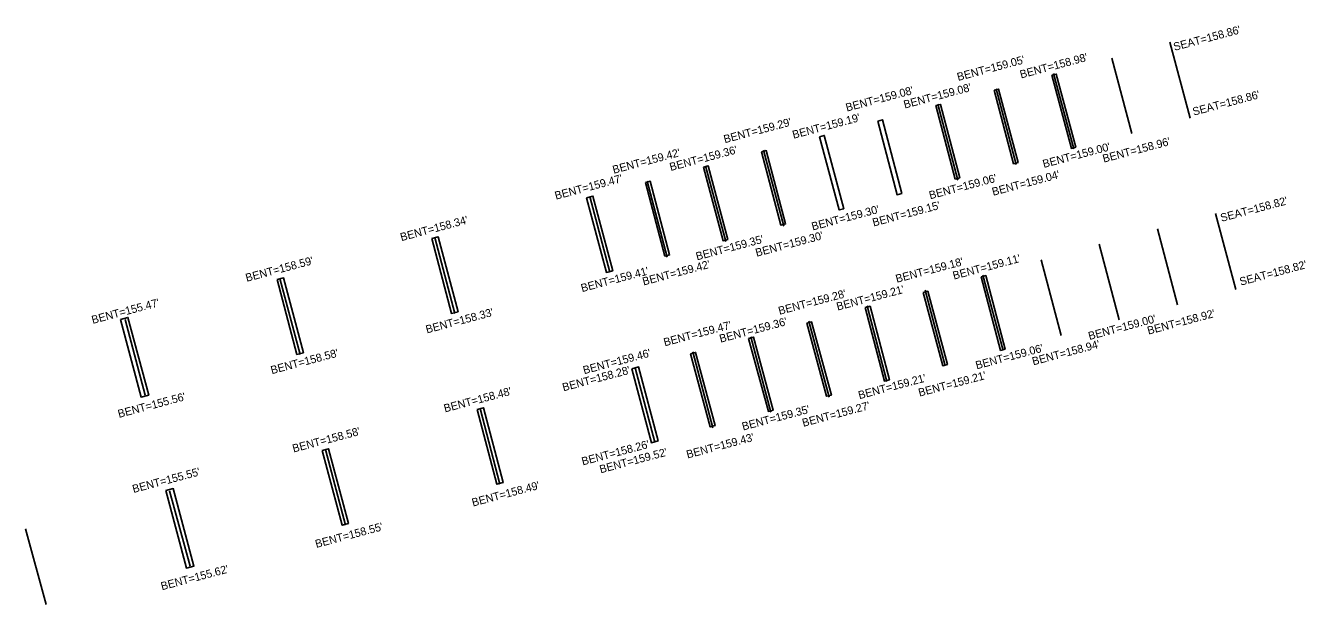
# Model space of a CAD drawing. Extents: x 2107167 to 2121551, y 865392 to 868477.
# Drawn here: x 2112084 to 2112723, y 867618 to 867908 of the extents above; entities that cross this region are included whole.
import ezdxf

# ---------------------------------------------------------------- set-up
doc = ezdxf.new("R2010")
doc.units = 0
for name, color, linetype in [('RD_EX_Bridge', 7, 'Continuous'), ('RD_EX_Bridge_txCode', 7, 'Continuous'), ('RD_EX_Conc', 7, 'Continuous')]:
    doc.layers.add(name, color=color, linetype=linetype)

msp = doc.modelspace()

# ---------------------------------------------------------------- linework, layer by layer
at = {"layer": 'RD_EX_Bridge'}
for p, q in [((2112655.33, 867899.22), (2112665.36, 867861.19)), ((2112626.2, 867891.32), (2112636.31, 867853.57)), ((2112597.18, 867883.66), (2112607.33, 867845.89)), ((2112568.42, 867875.92), (2112578.45, 867838.13)), ((2112539.39, 867868.24), (2112549.25, 867830.22)), ((2112452.27, 867845.19), (2112462.32, 867807.31)), ((2112423.24, 867837.47), (2112433.33, 867799.58)), ((2112394.16, 867829.78), (2112404.13, 867791.79)), ((2112365.42, 867822.14), (2112375.46, 867784.24)), ((2112678.14, 867813.68), (2112688.2, 867775.73)), ((2112287.94, 867801.6), (2112297.96, 867763.7)), ((2112659.13, 867768.06), (2112649.04, 867805.9)), ((2112630.01, 867760.43), (2112620, 867798.22)), ((2112600.87, 867752.72), (2112590.94, 867790.46)), ((2112210.58, 867781.17), (2112220.68, 867743.21)), ((2112571.89, 867745.14), (2112561.89, 867782.8)), ((2112542.94, 867737.45), (2112532.97, 867775.26)), ((2112513.88, 867729.71), (2112503.96, 867767.52)), ((2112133.18, 867760.62), (2112143.25, 867722.9)), ((2112484.98, 867721.93), (2112474.95, 867759.78)), ((2112455.9, 867714.38), (2112445.93, 867752.04)), ((2112426.98, 867706.59), (2112416.86, 867744.51)), ((2112397.97, 867699.38), (2112388.05, 867736.49)), ((2112310.62, 867716.13), (2112320.52, 867678.33)), ((2112233.3, 867695.72), (2112243.27, 867657.92)), ((2112155.42, 867675), (2112165.7, 867637.36)), ((2112083.5, 867656.11), (2112093.72, 867618.3))]:
    msp.add_line(p, q, dxfattribs=at)
at = {"layer": 'RD_EX_Conc'}
for points in [[(2112596.27, 867882.68), (2112606.05, 867846.14), (2112608.25, 867846.73), (2112598.46, 867883.26)], [(2112596.27, 867882.68), (2112606.05, 867846.14), (2112608.25, 867846.73), (2112598.46, 867883.26)], [(2112567.44, 867875.19), (2112577.18, 867838.48), (2112579.45, 867839.08), (2112569.7, 867875.79)], [(2112567.44, 867875.19), (2112577.18, 867838.48), (2112579.45, 867839.08), (2112569.7, 867875.79)], [(2112547.95, 867830.86), (2112538.4, 867867.51), (2112540.7, 867868.11), (2112550.26, 867831.46)], [(2112547.95, 867830.86), (2112538.4, 867867.51), (2112540.7, 867868.11), (2112550.26, 867831.46)], [(2112509.37, 867859.84), (2112519, 867823.03), (2112521.26, 867823.62), (2112511.63, 867860.43)], [(2112509.37, 867859.84), (2112519, 867823.03), (2112521.26, 867823.62), (2112511.63, 867860.43)], [(2112480.25, 867851.99), (2112490.04, 867815.38), (2112492.34, 867816), (2112482.55, 867852.6)], [(2112480.25, 867851.99), (2112490.04, 867815.38), (2112492.34, 867816), (2112482.55, 867852.6)], [(2112451.23, 867844.39), (2112460.87, 867807.81), (2112463.27, 867808.44), (2112453.63, 867845.03)], [(2112451.23, 867844.39), (2112460.87, 867807.81), (2112463.27, 867808.44), (2112453.63, 867845.03)], [(2112422.27, 867836.78), (2112432.01, 867800.03), (2112434.34, 867800.65), (2112424.6, 867837.39)], [(2112422.27, 867836.78), (2112432.01, 867800.03), (2112434.34, 867800.65), (2112424.6, 867837.39)], [(2112393.25, 867829.12), (2112402.96, 867792.33), (2112405.3, 867792.95), (2112395.59, 867829.74)], [(2112393.25, 867829.12), (2112402.96, 867792.33), (2112405.3, 867792.95), (2112395.59, 867829.74)], [(2112363.82, 867821.51), (2112373.74, 867784.21), (2112376.89, 867785.05), (2112366.96, 867822.35)], [(2112363.82, 867821.51), (2112373.74, 867784.21), (2112376.89, 867785.05), (2112366.96, 867822.35)], [(2112286.42, 867801.07), (2112296.29, 867763.7), (2112299.57, 867764.56), (2112289.7, 867801.93)], [(2112286.42, 867801.07), (2112296.29, 867763.7), (2112299.57, 867764.56), (2112289.7, 867801.93)], [(2112209.17, 867780.6), (2112219.11, 867743.19), (2112222.34, 867744.04), (2112212.39, 867781.45)], [(2112209.17, 867780.6), (2112219.11, 867743.19), (2112222.34, 867744.04), (2112212.39, 867781.45)], [(2112560.95, 867782.03), (2112570.65, 867745.22), (2112572.97, 867745.83), (2112563.27, 867782.64)], [(2112560.95, 867782.03), (2112570.65, 867745.22), (2112572.97, 867745.83), (2112563.27, 867782.64)], [(2112531.97, 867774.16), (2112541.78, 867737.55), (2112544.12, 867738.18), (2112534.3, 867774.79)], [(2112531.97, 867774.16), (2112541.78, 867737.55), (2112544.12, 867738.18), (2112534.3, 867774.79)], [(2112503.04, 867766.67), (2112512.66, 867729.88), (2112515.12, 867730.52), (2112505.49, 867767.31)], [(2112503.04, 867766.67), (2112512.66, 867729.88), (2112515.12, 867730.52), (2112505.49, 867767.31)], [(2112130.86, 867760.72), (2112141.23, 867721.88), (2112145.01, 867722.89), (2112134.64, 867761.73)], [(2112130.86, 867760.72), (2112141.23, 867721.88), (2112145.01, 867722.89), (2112134.64, 867761.73)], [(2112473.83, 867758.83), (2112483.69, 867722.27), (2112486.14, 867722.93), (2112476.27, 867759.49)], [(2112473.83, 867758.83), (2112483.69, 867722.27), (2112486.14, 867722.93), (2112476.27, 867759.49)], [(2112444.79, 867751.17), (2112454.67, 867714.69), (2112457.1, 867715.35), (2112447.22, 867751.83)], [(2112444.79, 867751.17), (2112454.67, 867714.69), (2112457.1, 867715.35), (2112447.22, 867751.83)], [(2112415.77, 867743.58), (2112425.64, 867707), (2112428.1, 867707.66), (2112418.24, 867744.24)], [(2112415.77, 867743.58), (2112425.64, 867707), (2112428.1, 867707.66), (2112418.24, 867744.24)], [(2112386.44, 867736.06), (2112396.24, 867699.08), (2112399.56, 867699.96), (2112389.76, 867736.94)], [(2112386.44, 867736.06), (2112396.24, 867699.08), (2112399.56, 867699.96), (2112389.76, 867736.94)], [(2112309.07, 867715.72), (2112318.99, 867678.35), (2112322.15, 867679.19), (2112312.23, 867716.56)], [(2112309.07, 867715.72), (2112318.99, 867678.35), (2112322.15, 867679.19), (2112312.23, 867716.56)], [(2112231.76, 867695.21), (2112241.69, 867657.85), (2112244.84, 867658.68), (2112234.9, 867696.04)], [(2112231.76, 867695.21), (2112241.69, 867657.85), (2112244.84, 867658.68), (2112234.9, 867696.04)], [(2112153.52, 867675.18), (2112163.85, 867636.47), (2112167.6, 867637.47), (2112157.27, 867676.18)], [(2112153.52, 867675.18), (2112163.85, 867636.47), (2112167.6, 867637.47), (2112157.27, 867676.18)]]:
    msp.add_lwpolyline(points, close=True, dxfattribs=at)

# ---------------------------------------------------------------- texts
at = {"layer": 'RD_EX_Bridge_txCode'}
for s, p in [("SEAT=158.86'", (2112657.62, 867894.88)), ("BENT=159.05'", (2112549.5, 867879.84)), ("BENT=158.98'", (2112580.91, 867881.08)), ("BENT=159.08'", (2112493.88, 867864.53)), ("BENT=159.08'", (2112522.8, 867866.03)), ("SEAT=158.86'", (2112667.2, 867862.48)), ("BENT=159.29'", (2112432.89, 867848.72)), ("BENT=159.19'", (2112467.22, 867850.93)), ("BENT=158.96'", (2112622.25, 867839.01)), ("BENT=159.42'", (2112377.37, 867833.45)), ("BENT=159.36'", (2112405.85, 867834.84)), ("BENT=159.00'", (2112592.28, 867836.37)), ("BENT=159.47'", (2112348.49, 867820.51)), ("BENT=159.06'", (2112535.51, 867820.69)), ("BENT=159.04'", (2112566.97, 867822.45)), ("BENT=159.15'", (2112507.23, 867807.09)), ("SEAT=158.82'", (2112681.11, 867809.44)), ("BENT=159.30'", (2112476.81, 867805.11)), ("BENT=158.34'", (2112271.29, 867799.78)), ("BENT=159.35'", (2112419, 867790.18)), ("BENT=159.30'", (2112448.77, 867791.99)), ("BENT=158.59'", (2112193.98, 867779.46)), ("BENT=159.42'", (2112392.31, 867777.63)), ("BENT=159.18'", (2112518.81, 867778.98)), ("BENT=159.11'", (2112547.37, 867780.57)), ("SEAT=158.82'", (2112690.69, 867777.56)), ("BENT=159.41'", (2112361.56, 867774.32)), ("BENT=159.28'", (2112460.21, 867762.97)), ("BENT=159.21'", (2112489.26, 867765.09)), ("BENT=155.47'", (2112117.06, 867758.43)), ("BENT=158.33'", (2112284.02, 867753.66)), ("BENT=159.00'", (2112615.08, 867750.39)), ("BENT=158.92'", (2112644.56, 867753.07)), ("BENT=159.47'", (2112402.88, 867747.24)), ("BENT=159.36'", (2112430.77, 867749.04)), ("BENT=158.94'", (2112587.01, 867737.72)), ("BENT=158.58'", (2112206.54, 867733.31)), ("BENT=159.46'", (2112362.6, 867733.29)), ("BENT=159.06'", (2112558.75, 867735.74)), ("BENT=158.28'", (2112352.28, 867724.74)), ("BENT=159.21'", (2112500.14, 867720.8)), ("BENT=159.21'", (2112530.17, 867722.09)), ("BENT=155.56'", (2112130.18, 867711.48)), ("BENT=158.48'", (2112293.06, 867714.21)), ("BENT=159.35'", (2112442.03, 867705.17)), ("BENT=159.27'", (2112472.12, 867707)), ("BENT=158.58'", (2112217.41, 867694.17)), ("BENT=158.26'", (2112361.91, 867687.73)), ("BENT=159.43'", (2112414.26, 867691.19)), ("BENT=159.52'", (2112370.86, 867683.78)), ("BENT=155.55'", (2112137.43, 867673.95)), ("BENT=158.49'", (2112307.06, 867667.17)), ("BENT=158.55'", (2112228.78, 867646.49)), ("BENT=155.62'", (2112151.66, 867625.34))]:
    msp.add_text(s, height=4, rotation=14.85803, dxfattribs=at).set_placement(p)

doc.saveas('drawing.dxf')
